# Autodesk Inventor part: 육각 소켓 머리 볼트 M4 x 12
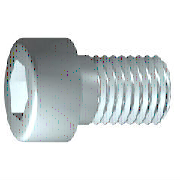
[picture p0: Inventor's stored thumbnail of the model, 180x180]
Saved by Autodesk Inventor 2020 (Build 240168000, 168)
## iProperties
Created: 2012-02
Part Number: 육각 소켓 머리 볼트 M4 x 12
Material: 강철, 연강
Description: 6각 소켓 머리 캡 나사
Document SubType Name: Modeling
Standard: ISO 4762
Designer: mdu-01
Standard Revision: Fourth edition 2004-03-01
Standards Organization: ISO
Language: ko-KR
Size Designation: M4 x 12
Categories: <MemberInstance><Categories><Category DisplayName="조임쇠" InternalName="e4da775c-781d-43d5-af7c-5136215cf5a6" Mnemonic="FSTN"><Category DisplayName="볼트" InternalN
Density: 7.75 g/cm^3
Appearance: 강철
IsCustomPart: 1
Author: mdu-01
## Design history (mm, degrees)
sketch "스케치1"
  geometry: L1 (-1, 0)-(12, 0); L2 (12, 0)-(12, 2); L3 (12, 2)-(1.75, 2); L4 (1.75, 2)-(1.32, 2); L5 (1.32, 2)-(0, 2); L6 (0, 2)-(0, 3.5); L7 (0, 3.5)-(-4, 3.5); L8 (-4, 3.5)-(-4, 1.732); L9 (-4, 1.732)-(-2, 1.732); L10 (-2, 1.732)-(-1, 0); L11 (-7.2, 0)-(15.2, 0) reference; L12 (0, -0.7)-(0, 4.2) reference; L13 (1.75, 2)-(0, 2)
  constraints: 22 end point, 6 parallel, 2 collinear, 2 perpendicular, 1 horizontal, 1 point on line
  dimensions: "d1" = 10.25 distance from line of L3.end L2 (= GEL); "d2" = 0.42952 distance of L4.end L3.end (computed from GAL); "d3" = 4 distance between parallel lines of L8 L6 (= KOH); "d4" = 2 distance of L8.end L9.end (= INTI); "d5" = 60 deg angle of L10 L1; "d6" = 4 diameter of L3 L1 (= GD); "d7" = 4 diameter of L5 L1 (= BDM); "d8" = 3.4641 diameter of L9 L1 (= 1.1547 x SW); "d9" = 7 diameter of L7 L1 (= KOD); "d26" = 12 distance between parallel lines of L12 L2 (= NLG)
revolve "본체" sketch "스케치1" stored, may be unused: angle "d10" = 90 deg
sketch "스케치2"
  geometry: L1 (0, -4.9)-(0, 4.9) reference; L2 (-4.9, 0)-(4.9, 0) reference; L3 (1.732, 0)-(0.866, -1.5); L4 (0.866, -1.5)-(-0.866, -1.5); L5 (-0.866, -1.5)-(-1.732, 0); L6 (-1.732, 0)-(-0.866, 1.5); L7 (-0.866, 1.5)-(0.866, 1.5); L8 (0.866, 1.5)-(1.732, 0); 2 further points
  constraints: 12 end point, 1 coincident, 1 horizontal alignment, 1 point on line, 12 other
extrude "슬롯" join sketch "스케치2" stored distance "d11" = 10; taper "d12" = 0 deg
workplane "Work Plane1"
fillet "Fillet2" dims "d30" = 0.1 (= R)
body "Solid1"
fillet "모깎기1" dims "d17" = 0.4 (= RR)
feature "스레드" dims "d13" = 10.25 (= GEL), "d14" = 0
chamfer "모따기1" distance "d15" = 0.42941 (= -0.5 x SPD + 0.5 x GD); stored, may be unused: second distance "d16" = 0.42941 (= GUL), angle "d27" = 45 deg
other parameters: "GD" = 4 [user parameter; used in 2 equation terms], "NLG" = 12 [user parameter; used in 1 equation term], "GEL" = 10.25 [user parameter; used in 2 equation terms], "KOD" = 7 [user parameter; used in 1 equation term], "KOH" = 4 [user parameter; used in 1 equation term], "INTI" = 2 [user parameter; used in 1 equation term], "GAL" = 0.42941 (= 0.61345 x PTC) [user parameter; used in 1 equation term], "GUL" = 0.42941 (= 0.61345 x PTC) [user parameter; used in 1 equation term], "BDM" = 4 (= NND) [user parameter; used in 1 equation term], "SW" = 3 [user parameter; used in 2 equation terms], "RR" = 0.4 [user parameter; used in 1 equation term], "SPD" = 3.14117 (= NND - 1.2269 x PTC) [user parameter; used in 1 equation term], "d19" = 0, "d28" = 0, "d29" = 0, "R" = 0.1 [user parameter; used in 1 equation term], "TOA" = 30 deg [user parameter], "GD1" = 3.14117 (= THREADDIA - 1.2269 x PTC) [user parameter], "THREADDIA" = 4 [user parameter; used in 1 equation term], "FAWI" = 45 deg [user parameter], "TPU" = 14.28571 (computed from PTC) [user parameter], "PTC" = 0.7 [user parameter; used in 5 equation terms], "NND" = 4 [user parameter; used in 2 equation terms], "E0" = 3.465 (= 1.155 x SW) [user parameter]
